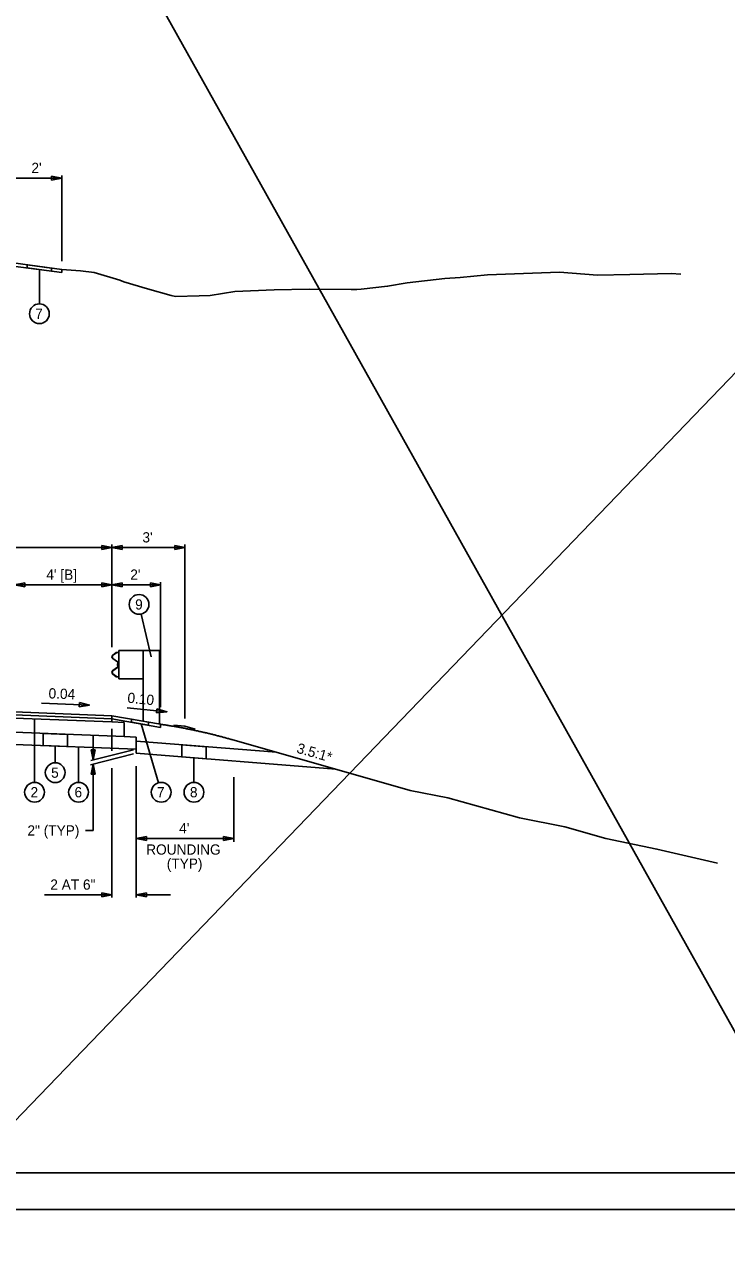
# Model space of a CAD drawing. Extents: x -396 to 156, y -166 to 172.
# Drawn here: x -297.2 to -268.4, y -66 to -15.8 of the extents above; entities that cross this region are included whole.
import ezdxf

# ---------------------------------------------------------------- set-up
doc = ezdxf.new("R2010")
doc.units = 0
for name, color, linetype in [('DT_X_Terrain_Ground_Line', 7, 'Continuous'), ('RD_P_Cells', 7, 'Continuous'), ('SH_Border', 7, 'Continuous'), ('SH_Cut_Line', 7, 'Continuous'), ('TX_P_1', 7, 'Continuous'), ('TX_X_1', 7, 'Continuous'), ('XS_P_Finished_Grade', 7, 'Continuous'), ('XS_P_Pavt_Surface', 7, 'Continuous')]:
    doc.layers.add(name, color=color, linetype=linetype)

msp = doc.modelspace()

# ---------------------------------------------------------------- linework, layer by layer
at = {"layer": 'DT_X_Terrain_Ground_Line'}
for points in [[(-295.712, -25.893), (-294.941, -25.941), (-294.384, -26.018), (-293.332, -26.329), (-293.167, -26.399), (-292.195, -26.687), (-291.224, -26.965), (-291.036, -26.998), (-290.067, -26.978), (-289.612, -26.959), (-288.608, -26.797), (-286.984, -26.724), (-285.545, -26.703), (-283.825, -26.714), (-283.587, -26.714), (-283.412, -26.698), (-282.332, -26.579), (-281.524, -26.436), (-279.985, -26.268), (-279.344, -26.22), (-278.222, -26.117), (-275.262, -26.008), (-273.711, -26.128), (-272.379, -26.093), (-270.687, -26.054), (-270.287, -26.089)], [(-281.406, -47.291), (-279.859, -47.587), (-276.913, -48.414), (-275.044, -48.787), (-273.37, -49.259), (-271.265, -49.694), (-268.774, -50.275)]]:
    msp.add_lwpolyline(points, dxfattribs=at)
at = {"layer": 'RD_P_Cells'}
for p, q in [((-293.473, -41.623), (-293.616, -41.73)), ((-293.386, -41.608), (-293.473, -41.623)), ((-293.473, -41.623), (-293.473, -41.623)), ((-293.469, -41.632), (-293.386, -41.618)), ((-293.386, -41.608), (-293.386, -41.608)), ((-293.386, -41.618), (-293.386, -41.608)), ((-293.386, -41.618), (-293.386, -41.618)), ((-293.371, -41.536), (-292.371, -41.536)), ((-293.371, -42.703), (-293.371, -41.536)), ((-292.371, -41.536), (-291.704, -41.536)), ((-292.371, -44.441), (-292.371, -41.536)), ((-291.704, -44.565), (-291.704, -41.536)), ((-293.652, -41.801), (-293.652, -41.801)), ((-293.642, -41.801), (-293.642, -41.801)), ((-293.616, -41.73), (-293.616, -41.73)), ((-293.616, -41.872), (-293.616, -41.872)), ((-293.616, -41.872), (-293.429, -42.01)), ((-293.61, -41.738), (-293.469, -41.632)), ((-293.61, -41.738), (-293.61, -41.738)), ((-293.61, -41.864), (-293.61, -41.864)), ((-293.423, -42.002), (-293.61, -41.864)), ((-293.496, -41.64), (-293.496, -41.64)), ((-293.496, -41.96), (-293.496, -41.96)), ((-293.491, -41.648), (-293.491, -41.648)), ((-293.49, -41.952), (-293.49, -41.952)), ((-293.469, -41.632), (-293.469, -41.632)), ((-293.429, -42.01), (-293.429, -42.01)), ((-293.423, -42.002), (-293.423, -42.002)), ((-293.396, -42.073), (-293.397, -42.165)), ((-293.397, -42.151), (-293.396, -42.088)), ((-293.396, -42.073), (-293.396, -42.073)), ((-293.387, -42.073), (-293.387, -42.073)), ((-293.387, -42.165), (-293.387, -42.073)), ((-293.387, -42.151), (-293.387, -42.088)), ((-293.653, -42.437), (-293.653, -42.437)), ((-293.643, -42.437), (-293.643, -42.437)), ((-293.618, -42.508), (-293.618, -42.508)), ((-293.618, -42.508), (-293.475, -42.616)), ((-293.429, -42.229), (-293.617, -42.366)), ((-293.617, -42.366), (-293.617, -42.366)), ((-293.612, -42.5), (-293.612, -42.5)), ((-293.471, -42.606), (-293.612, -42.5)), ((-293.611, -42.374), (-293.423, -42.237)), ((-293.611, -42.374), (-293.611, -42.374)), ((-293.475, -42.616), (-293.388, -42.631)), ((-293.388, -42.621), (-293.471, -42.606)), ((-293.429, -42.229), (-293.429, -42.229)), ((-293.423, -42.237), (-293.423, -42.237)), ((-293.397, -42.165), (-293.397, -42.165)), ((-293.388, -42.621), (-293.388, -42.621)), ((-293.388, -42.631), (-293.388, -42.621)), ((-293.387, -42.165), (-293.387, -42.165)), ((-293.388, -42.631), (-293.388, -42.631)), ((-293.371, -42.703), (-292.371, -42.703))]:
    msp.add_line(p, q, dxfattribs=at)
for points in [[(-293.405, -42.091), (-293.405, -42.149), (-293.43, -42.149), (-293.43, -42.091)], [(-293.405, -42.059), (-293.405, -42.179), (-293.397, -42.179), (-293.397, -42.059)]]:
    msp.add_lwpolyline(points, close=True, dxfattribs=at)
for centre, radius, start, end in [((-293.563, -41.801), 0.0886, 126.7788, 233.682), ((-293.563, -41.801), 0.0787, 126.7788, 233.682), ((-293.475, -42.073), 0.0788, 359.9056, 53.682), ((-293.475, -42.073), 0.0886, 359.9056, 53.682), ((-293.564, -42.437), 0.0886, 126.1293, 233.0325), ((-293.564, -42.437), 0.0787, 126.1293, 233.0325), ((-293.475, -42.165), 0.0788, 306.1293, 359.9056), ((-293.475, -42.165), 0.0886, 306.1293, 359.9056)]:
    msp.add_arc(centre, radius, start, end, dxfattribs=at)
at = {"layer": 'SH_Border'}
msp.add_lwpolyline([(-354.402, 0.004), (-258.402, 0.004), (-258.402, -62.996), (-354.402, -62.996)], close=True, dxfattribs=at)
at = {"layer": 'SH_Cut_Line'}
for points in [[(-358.902, -64.496), (-256.902, -64.496), (-256.902, 1.504), (-358.902, 1.504)], [(-358.902, -130.496), (-256.902, -130.496), (-256.902, -64.496), (-358.902, -64.496)]]:
    msp.add_lwpolyline(points, close=True, dxfattribs=at)
at = {"layer": 'TX_P_1'}
for p, q in [((-296.132, -22.057), (-296.132, -22.225)), ((-295.712, -25.554), (-295.712, -22.029)), ((-295.712, -22.141), (-297.712, -22.141)), ((-293.652, -37.313), (-308.652, -37.313)), ((-294.072, -37.229), (-294.072, -37.397)), ((-293.652, -41.403), (-293.652, -37.193)), ((-293.652, -37.313), (-290.652, -37.313)), ((-293.232, -37.397), (-293.232, -37.229)), ((-291.072, -37.229), (-291.072, -37.397)), ((-290.652, -44.339), (-290.652, -37.193)), ((-297.652, -38.844), (-293.652, -38.844)), ((-297.232, -38.928), (-297.232, -38.76)), ((-294.072, -38.76), (-294.072, -38.928)), ((-291.652, -38.844), (-293.652, -38.844)), ((-293.232, -38.928), (-293.232, -38.76)), ((-292.072, -38.76), (-292.072, -38.928)), ((-291.652, -43.87), (-291.652, -38.735)), ((-294.575, -43.783), (-296.553, -43.704)), ((-294.992, -43.682), (-294.998, -43.85)), ((-291.397, -44.056), (-293.034, -43.893)), ((-291.806, -43.931), (-291.823, -44.098)), ((-294.421, -45.063), (-294.421, -46.036)), ((-293.652, -45.663), (-293.652, -44.754)), ((-292.761, -45.624), (-294.515, -46.059)), ((-294.337, -45.616), (-294.505, -45.616)), ((-292.652, -45.263), (-286.892, -45.723)), ((-292.652, -45.598), (-292.652, -45.764)), ((-292.761, -45.791), (-294.536, -46.231)), ((-292.652, -45.764), (-284.454, -46.42)), ((-294.505, -46.623), (-294.337, -46.623)), ((-294.421, -46.203), (-294.421, -48.932)), ((-293.652, -46.367), (-293.652, -51.681)), ((-292.652, -46.288), (-292.652, -51.681)), ((-288.652, -46.741), (-288.652, -49.404)), ((-294.741, -48.932), (-294.421, -48.932)), ((-292.652, -49.26), (-288.652, -49.26)), ((-292.232, -49.344), (-292.232, -49.176)), ((-289.072, -49.176), (-289.072, -49.344)), ((-293.652, -51.575), (-296.421, -51.575)), ((-294.072, -51.659), (-294.072, -51.491)), ((-291.25, -51.575), (-292.652, -51.575)), ((-292.232, -51.491), (-292.232, -51.659))]:
    msp.add_line(p, q, dxfattribs=at)
for points in [[(-296.132, -22.225), (-295.712, -22.141), (-296.132, -22.057)], [(-294.072, -37.397), (-293.652, -37.313), (-294.072, -37.229)], [(-293.232, -37.229), (-293.652, -37.313), (-293.232, -37.397)], [(-291.072, -37.397), (-290.652, -37.313), (-291.072, -37.229)], [(-297.232, -38.76), (-297.652, -38.844), (-297.232, -38.928)], [(-294.072, -38.928), (-293.652, -38.844), (-294.072, -38.76)], [(-293.232, -38.76), (-293.652, -38.844), (-293.232, -38.928)], [(-292.072, -38.928), (-291.652, -38.844), (-292.072, -38.76)], [(-294.998, -43.85), (-294.575, -43.783), (-294.992, -43.682)], [(-291.823, -44.098), (-291.397, -44.056), (-291.806, -43.931)], [(-291.107, -44.604), (-290.652, -44.649), (-290.239, -44.767)], [(-294.505, -45.616), (-294.421, -46.036), (-294.337, -45.616)], [(-294.337, -46.623), (-294.421, -46.203), (-294.505, -46.623)], [(-292.232, -49.176), (-292.652, -49.26), (-292.232, -49.344)], [(-289.072, -49.344), (-288.652, -49.26), (-289.072, -49.176)], [(-294.072, -51.491), (-293.652, -51.575), (-294.072, -51.659)], [(-292.232, -51.659), (-292.652, -51.575), (-292.232, -51.491)]]:
    msp.add_lwpolyline(points, dxfattribs=at)
for centre in [(-296.633, -27.709), (-292.538, -39.649), (-295.983, -46.558), (-296.832, -47.362), (-295.025, -47.362), (-291.63, -47.362), (-290.284, -47.362)]:
    msp.add_circle(centre, 0.406, dxfattribs=at)
at = {"layer": 'TX_X_1'}
for p, q in [((-297.133, -25.827), (-297.133, -25.702)), ((-296.633, -27.303), (-296.633, -25.894)), ((-296.133, -25.961), (-296.133, -25.836)), ((-292.447, -40.045), (-292.044, -41.799)), ((-296.832, -46.956), (-296.832, -44.347)), ((-292.856, -44.362), (-292.856, -44.487)), ((-291.745, -46.973), (-292.459, -44.557)), ((-292.156, -44.484), (-292.156, -44.609)), ((-296.483, -45.444), (-296.483, -44.944)), ((-295.483, -45.484), (-295.483, -44.984)), ((-295.983, -46.151), (-295.983, -45.464)), ((-295.025, -46.956), (-295.025, -45.503)), ((-290.784, -45.914), (-290.784, -45.412)), ((-289.784, -45.994), (-289.784, -45.492)), ((-290.284, -46.956), (-290.284, -45.954))]:
    msp.add_line(p, q, dxfattribs=at)
for points in [[(-296.133, -25.961), (-297.133, -25.827), (-297.133, -25.702), (-296.133, -25.836)], [(-292.156, -44.609), (-292.856, -44.487), (-292.856, -44.362), (-292.156, -44.484)], [(-295.483, -45.484), (-296.483, -45.444), (-296.483, -44.944), (-295.483, -44.984)], [(-289.784, -45.492), (-289.784, -45.994), (-290.784, -45.914), (-290.784, -45.412)]]:
    msp.add_lwpolyline(points, close=True, dxfattribs=at)
at = {"layer": 'XS_P_Finished_Grade'}
for p, q in [((-396.097, 171.685), (-207.077, -166.247)), ((-88.939, 155.921), (-374.438, -140.631)), ((-288.721, -45.201), (-281.406, -47.291))]:
    msp.add_line(p, q, dxfattribs=at)
msp.add_spline([(-291.652, -44.572), (-291.579, -44.583), (-291.503, -44.594), (-291.427, -44.606), (-291.351, -44.618), (-291.275, -44.63), (-291.199, -44.642), (-291.123, -44.655), (-291.047, -44.668), (-290.971, -44.681), (-290.896, -44.695), (-290.82, -44.709), (-290.744, -44.723), (-290.669, -44.737), (-290.593, -44.752), (-290.518, -44.767), (-290.442, -44.782), (-290.367, -44.797), (-290.292, -44.813), (-290.216, -44.829), (-290.141, -44.845), (-290.066, -44.861), (-289.991, -44.878), (-289.916, -44.895), (-289.841, -44.912), (-289.766, -44.929), (-289.691, -44.947), (-289.616, -44.965), (-289.541, -44.983), (-289.466, -45.002), (-289.392, -45.02), (-289.317, -45.039), (-289.242, -45.059), (-289.168, -45.078), (-289.093, -45.098), (-289.019, -45.118), (-288.944, -45.138), (-288.87, -45.159), (-288.795, -45.18), (-288.721, -45.201)], degree=3, dxfattribs=at)
at = {"layer": 'XS_P_Pavt_Surface'}
for p, q in [((-297.712, -25.625), (-295.712, -25.893)), ((-297.712, -25.75), (-295.712, -26.017)), ((-295.712, -25.893), (-295.712, -26.017)), ((-297.652, -44.064), (-293.652, -44.224)), ((-297.652, -44.189), (-293.652, -44.349)), ((-297.652, -44.314), (-293.652, -44.474)), ((-293.652, -44.224), (-293.652, -44.474)), ((-293.652, -44.224), (-291.652, -44.572)), ((-293.652, -44.349), (-291.652, -44.697)), ((-293.652, -44.474), (-293.152, -44.494)), ((-293.152, -44.494), (-293.152, -45.078)), ((-291.652, -44.572), (-291.652, -44.697)), ((-297.652, -44.898), (-293.152, -45.078)), ((-293.152, -45.078), (-292.652, -45.098)), ((-292.652, -45.098), (-292.652, -45.598)), ((-297.652, -45.398), (-292.652, -45.598))]:
    msp.add_line(p, q, dxfattribs=at)

# ---------------------------------------------------------------- texts
at = {"layer": 'TX_P_1'}
for s, p in [("2'", (-296.96, -21.931)), ('7', (-296.807, -27.919)), ("3'", (-292.4, -37.103)), ("4' [B]", (-296.348, -38.634)), ("2'", (-292.9, -38.634)), ('9', (-292.7, -39.859)), ('5', (-296.151, -46.768)), ('2', (-296.997, -47.572)), ('6', (-295.191, -47.572)), ('7', (-291.804, -47.572)), ('8', (-290.449, -47.572)), ("4'", (-290.891, -49.05)), ('2" (TYP)', (-297.124, -49.142)), ('ROUNDING', (-292.246, -49.925)), ('(TYP)', (-291.401, -50.507)), ('2 AT 6"', (-296.185, -51.365))]:
    msp.add_text(s, height=0.42, dxfattribs=at).set_placement(p)
for s, rotation, p in [('0.04', 357.7094, (-296.263, -43.505)), ('3.5:1*', 344.0546, (-286.095, -45.733))]:
    msp.add_text(s, height=0.42, rotation=rotation, dxfattribs=at).set_placement(p)
at = {"layer": 'XS_P_Finished_Grade'}
msp.add_text('0.10', height=0.42, rotation=354.2894, dxfattribs=at).set_placement((-293.032, -43.682))

doc.saveas('drawing.dxf')
